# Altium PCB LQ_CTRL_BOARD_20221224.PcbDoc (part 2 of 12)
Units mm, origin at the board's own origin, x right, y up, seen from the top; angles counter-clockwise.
Board outline 260 x 142 mm, 6 copper layers (Top Layer, Mid-Layer 1, Mid-Layer 2, Mid-Layer 3, Mid-Layer 4, Bottom Layer); 1105 components, 1039 nets, 3898 pads, 1277 vias.
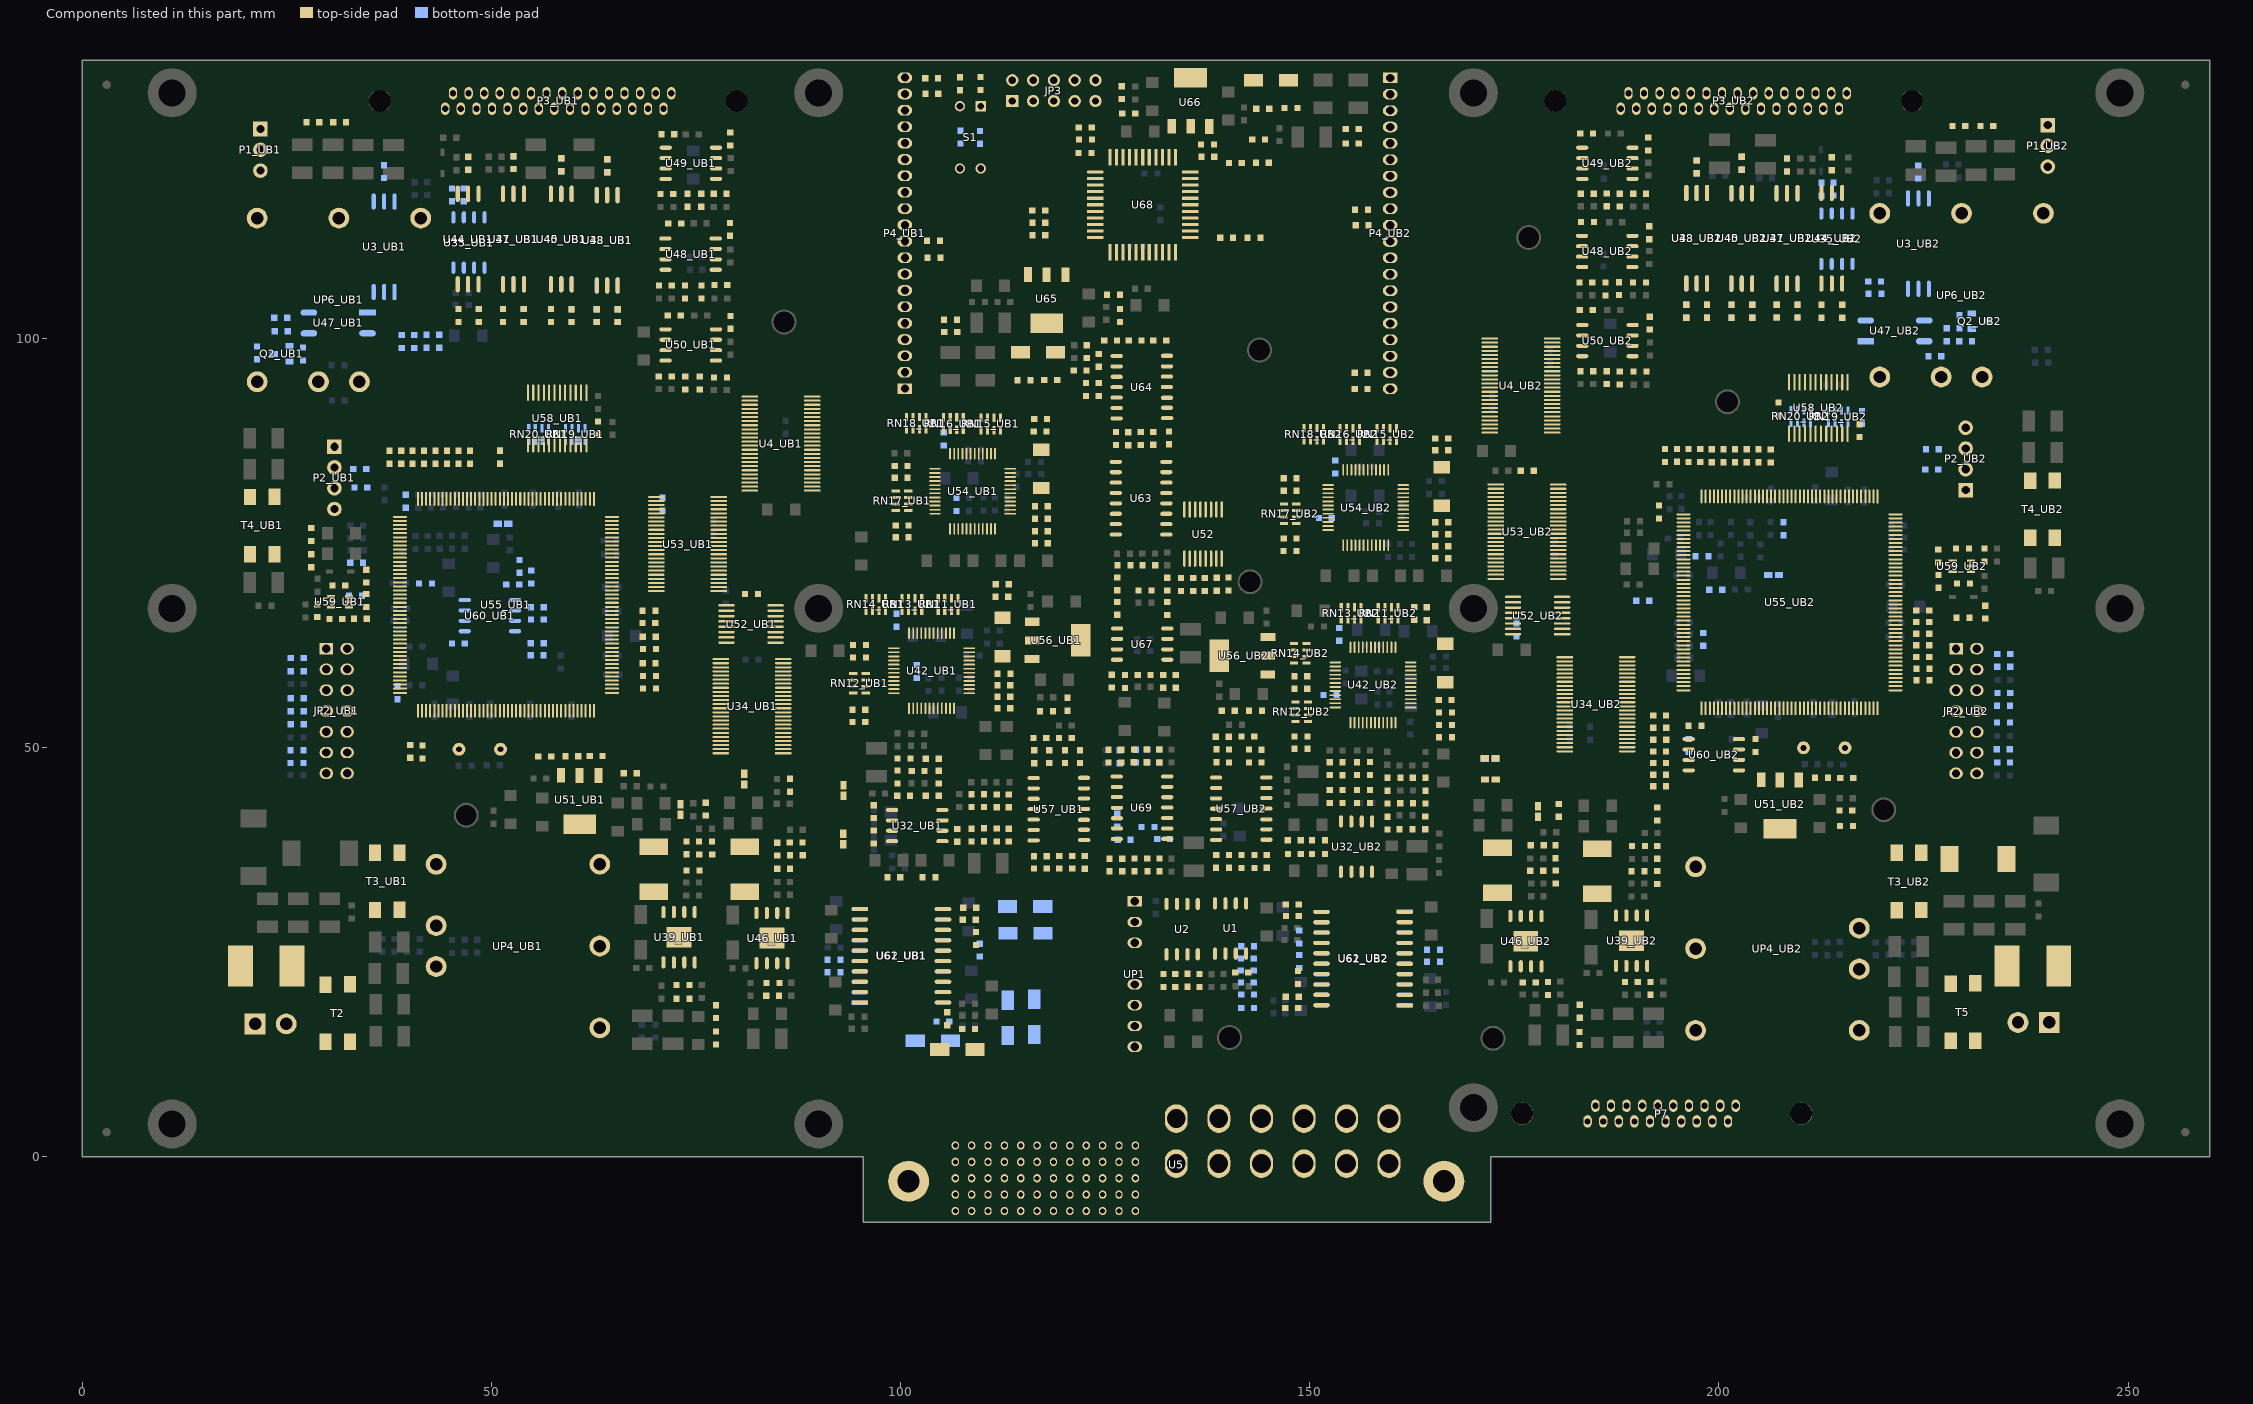
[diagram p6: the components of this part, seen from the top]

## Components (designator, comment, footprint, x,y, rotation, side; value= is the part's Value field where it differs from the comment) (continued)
DR2_UB2 "SMCJ30CA-TR" WP_SMC_DO214AB 228.168,36.373 r0 top (schematic designator DR2)
DR3 "SMCJ12CA-TR" WP_SMA_DO214AC 147.422,131.547 r180 top
DR4 "SMCJ5CA-TR" WP_SMA_DO214AC 114.656,98.298 r0 top
DR5 "SMAJ5.0CA" WP_SMA_DO214AC 101.803,14.173 r0 bottom
DR6 "SMAJ5.0CA" WP_SMA_DO214AC 117.373,30.582 r180 bottom
DR7 "SMAJ5.0CA" WP_SMA_DO214AC 104.8,13.106 r0 top
DR8 "SMAJ5.0CA" WP_SMA_DO214AC 117.424,27.305 r180 bottom
DR9 "SMAJ5.0CA" WP_SMA_DO214AC 116.357,14.935 r90 bottom
DR10 "SMAJ5.0CA" WP_SMA_DO214AC 113.106,14.808 r90 bottom
F1_UB1 "SMD2920R300SF" WP_2420 25.654,23.292 r180 top (schematic designator F1)
F1_UB2 "SMD2920R300SF" WP_2420 235.229,23.317 r0 top (schematic designator F1)
JP2_UB1 "JTAG" WP_IDC14 29.845,62.089 r270 top (schematic designator JP2)
JP2_UB2 "JTAG" WP_IDC14 228.981,62.078 r270 top (schematic designator JP2)
JP3 "Header 5X2" HDR2X5 113.665,129 r0 top
L3_UB1 "10uH/2A" WP_LBS6*6 69.85,37.897 r270 top (schematic designator L3)
L3_UB2 "10uH/2A" WP_LBS6*6 185.121,37.617 r270 top (schematic designator L3)
L4_UB1 "10uH/2A" WP_LBS6*6 80.975,37.871 r270 top (schematic designator L4)
L4_UB2 "10uH/2A" WP_LBS6*6 172.949,37.744 r270 top (schematic designator L4)
LED1 "LED" WP_0603_LED 145.009,121.463 r180 top
LED2 "LED" WP_0603_LED 143.993,112.293 r180 top
LED3 "LED" WP_0603_LED 109.779,131.928 r270 top
LED4 "LED" WP_0603_LED 107.264,131.902 r270 top
LED5_UB1 "LED" WP_0603_LED 27.991,76.81 r270 top (schematic designator LED5)
LED5_UB2 "LED" WP_0603_LED 232.537,67.335 r270 top (schematic designator LED5)
LED9_UB1 "LED" WP_0603_LED 77.47,18.517 r270 top (schematic designator LED9)
LED9_UB2 "LED" WP_0603_LED 183.007,18.567 r270 top (schematic designator LED9)
LED10_UB1 "LED" WP_0603_LED 27.407,126.39 r0 top (schematic designator LED10)
LED10_UB2 "LED" WP_0603_LED 233.528,125.959 r180 top (schematic designator LED10)
LED11_UB1 "LED" WP_0603_LED 60.63,48.946 r180 top (schematic designator LED11)
LED11_UB2 "LED" WP_0603_LED 214.732,42.316 r0 top (schematic designator LED11)
LED12_UB1 "LED" WP_0603_LED 120.416,56.083 r270 top (schematic designator LED12)
LED12_UB2 "LED" WP_0603_LED 139.268,54.487 r0 top (schematic designator LED12)
LED13_UB1 "LED" WP_0603_LED 40.107,50.317 r270 top (schematic designator LED13)
LED13_UB2 "LED" WP_0603_LED 191.973,53.899 r0 top (schematic designator LED13)
LED14_UB1 "LED" WP_0603_LED 107.62,28.956 r0 top (schematic designator LED14)
LED14_UB2 "LED" WP_0603_LED 148.655,19.558 r180 top (schematic designator LED14)
LED15_UB1 "LED" WP_0603_LED 105.715,17.653 r270 top (schematic designator LED15)
LED15_UB2 "LED" WP_0603_LED 148.655,30.81 r180 top (schematic designator LED15)
LED16 "LED" WP_0603_LED 114.3,94.869 r0 top
LED17 "LED" WP_0603_LED 148.514,128.143 r180 top
LED18 "LED" WP_0603_LED 126.822,102.006 r90 top
LED19 "LED" WP_0603_LED 127.045,130.81 r270 top
LED20 "LED" WP_0603_LED 123.393,124.282 r180 top
LED21 "LED" WP_0603_LED 136.728,123.673 r0 top
P1_UB1 "Header 3" WP_SIP3 21.793,125.578 r270 top (schematic designator P1)
P1_UB2 "Header 3" WP_SIP3 240.182,126.06 r270 top (schematic designator P1)
P2_UB1 "Header 4" WP_SIP4 30.836,86.766 r270 top (schematic designator P2)
P2_UB2 "Header 4" WP_SIP4 230.149,81.458 r90 top (schematic designator P2)
P3_UB1 "Header 15X2A" WP_CRM222-030 44.374,128.047 r180 bottom locked (schematic designator P3)
P3_UB2 "Header 15X2A" WP_CRM222-030 215.623,129.952 r0 bottom locked (schematic designator P3)
P4_UB1 "Header 20" WP_HEADER20S 100.533,93.853 r90 top (schematic designator P4)
P4_UB2 "Header 20" WP_HEADER20S 159.842,131.826 r270 top (schematic designator P4)
P7 "Header 10X2A" WP_CRM222-020 202.057,6.223 r0 bottom
P9_UB1 "Header 2" WP_LSIP2 21.133,16.231 r0 top (schematic designator P9)
P9_UB2 "Header 2" WP_LSIP2 240.36,16.408 r180 top (schematic designator P9)
Q2_UB1 "MMBT4401" WP_SOT23B 25.355,99.035 r270 bottom (schematic designator Q2)
Q2_UB2 "MMBT4401" WP_SOT23B 230.886,101.143 r90 bottom (schematic designator Q2)
R1 "0R" WP_0603R 105.334,102.26 r0 top
R2 "0R" WP_0603R 155.981,123.8 r180 top
R3_UB1 "100R" WP_0603R 45.999,84.684 r90 top (schematic designator R3)
R3_UB2 "100R" WP_0603R 203.403,84.861 r90 top (schematic designator R3)
R4_UB1 "100R" WP_0603R 47.396,84.684 r90 top (schematic designator R4)
R4_UB2 "100R" WP_0603R 204.826,84.861 r90 top (schematic designator R4)
R5 "2K" WP_0603R 134.264,70.714 r270 top
R6 "150R" WP_0603R 138.659,70.739 r270 top
R7 "150R" WP_0603R 140.081,70.764 r270 top
R8 "150R" WP_0603R 137.185,70.714 r270 top
R9 "150R" WP_0603R 135.763,70.714 r270 top
R10 "200R" WP_0603R 132.131,20.752 r90 top
R11 "200R" WP_0603R 135.077,20.777 r90 top
R12 "1K" WP_0603R 142.494,22.504 r180 top
R13 "200R" WP_0603R 133.579,20.752 r90 top
R14 "200R" WP_0603R 136.55,20.752 r90 top
R15_UB1 "0R" WP_0603R 38.532,55.905 r90 bottom (schematic designator R15)
R15_UB2 "0R" WP_0603R 198.095,64.008 r270 bottom (schematic designator R15)
R16_UB1 "0R" WP_0603R 41.173,70.053 r0 bottom (schematic designator R16)
R16_UB2 "0R" WP_0603R 198.831,69.291 r0 bottom (schematic designator R16)
R17_UB1 "1K5" WP_0603R 77.171,117.678 r0 top (schematic designator R17)
R17_UB2 "1K5" WP_0603R 189.535,117.653 r0 top (schematic designator R17)
R18_UB1 "1K5" WP_0603R 72.238,117.627 r180 top (schematic designator R18)
R18_UB2 "1K5" WP_0603R 184.709,117.653 r180 top (schematic designator R18)
R19_UB1 "1K5" WP_0603R 72.04,95.326 r180 top (schematic designator R19)
R19_UB2 "1K5" WP_0603R 184.658,95.987 r180 top (schematic designator R19)
R20_UB1 "1K5" WP_0603R 77.216,95.199 r0 top (schematic designator R20)
R20_UB2 "1K5" WP_0603R 189.572,95.936 r0 top (schematic designator R20)
R21_UB1 "1K5" WP_0603R 72.06,106.451 r180 top (schematic designator R21)
R21_UB2 "1K5" WP_0603R 184.531,106.807 r180 top (schematic designator R21)
R22_UB1 "1K5" WP_0603R 77.267,106.528 r0 top (schematic designator R22)
R22_UB2 "1K5" WP_0603R 189.509,106.832 r0 top (schematic designator R22)
R23_UB1 "150R" WP_0603R 62.89,101.981 r90 top (schematic designator R23)
R23_UB2 "150R" WP_0603R 198.557,102.514 r90 bottom (schematic designator R23)
R24 "10K" WP_0603R 131.648,36.449 r270 top
R25 "10K" WP_0603R 131.628,49.747 r270 top
R26_UB1 "150R" WP_0603R 43.643,98.857 r90 bottom (schematic designator R26)
R26_UB2 "150R" WP_0603R 218.237,106.959 r0 bottom (schematic designator R26)
R27_UB1 "150R" WP_0603R 42.093,98.857 r90 bottom (schematic designator R27)
R27_UB2 "150R" WP_0603R 218.288,105.435 r0 bottom (schematic designator R27)
R28_UB1 "33R" WP_0603R 36.906,119.583 r90 bottom (schematic designator R28)
R28_UB2 "33R" WP_0603R 224.358,119.532 r90 bottom (schematic designator R28)
R29_UB1 "33R" WP_0603R 34.722,84.023 r180 bottom (schematic designator R29)
R29_UB2 "33R" WP_0603R 225.222,83.972 r0 bottom (schematic designator R29)
R30_UB1 "33R" WP_0603R 33.274,81.763 r0 bottom (schematic designator R30)
R30_UB2 "33R" WP_0603R 226.873,86.436 r180 bottom (schematic designator R30)
R31 "2K" WP_0603R 141.707,121.437 r180 top
R32 "3K" WP_0603R 109.703,123.774 r90 bottom
R33 "2K" WP_0603R 140.64,112.293 r180 top
R34 "3K" WP_0603R 107.34,123.8 r90 bottom
R35 "10K" WP_0603R 116.129,112.598 r0 top
R36 "10K" WP_0603R 123.368,125.755 r180 top
R37 "10K" WP_0603R 116.129,114.122 r0 top
R38 "10K" WP_0603R 116.103,115.621 r0 top
R39_UB1 "10K" WP_0603R 105.283,88.494 r270 bottom (schematic designator R39)
R39_UB2 "10K" WP_0603R 153.111,85.065 r270 bottom (schematic designator R39)
R40_UB1 "10K" WP_0603R 99.517,66.345 r270 bottom (schematic designator R40)
R40_UB2 "10K" WP_0603R 153.619,64.618 r270 bottom (schematic designator R40)
R41_UB1 "2K" WP_0603R 27.991,72.034 r90 top (schematic designator R41)
R41_UB2 "2K" WP_0603R 229.033,65.862 r0 top (schematic designator R41)
R187 "10R" WP_0603R 126.492,40.335 r90 bottom
R188 "10R" WP_0603R 126.797,48.082 r90 bottom
R192_UB1 "10K" WP_0603R 45.212,116.738 r90 bottom (schematic designator R192)
R192_UB2 "10K" WP_0603R 212.547,117.424 r90 bottom (schematic designator R192)
R194_UB1 "2K" WP_0603R 46.634,116.738 r90 bottom (schematic designator R194)
R194_UB2 "2K" WP_0603R 214.02,117.45 r90 bottom (schematic designator R194)
R195_UB1 "10K" WP_0603R 104.663,47.168 r270 top (schematic designator R195)
R195_UB2 "10K" WP_0603R 164.16,44.729 r270 top (schematic designator R195)
R196_UB1 "100R" WP_0603R 104.663,44.12 r180 top (schematic designator R196)
R196_UB2 "100R" WP_0603R 164.109,41.586 r270 top (schematic designator R196)
R197_UB1 "620R" WP_0603R 108.681,42.723 r90 top (schematic designator R197)
R197_UB2 "620R" WP_0603R 152.451,46.634 r90 top (schematic designator R197)
R198_UB1 "100K" WP_0603R 104.267,34.163 r180 top (schematic designator R198)
R198_UB2 "100K" WP_0603R 147.345,36.982 r0 top (schematic designator R198)
R200_UB1 "100K" WP_0603R 108.687,38.506 r90 top (schematic designator R200)
R200_UB2 "100K" WP_0603R 152.451,43.231 r90 top (schematic designator R200)
R203_UB1 "100K" WP_0603R 103.099,48.641 r0 top (schematic designator R203)
R203_UB2 "100K" WP_0603R 162.585,46.31 r0 top (schematic designator R203)
R205_UB1 "100K" WP_0603R 110.211,38.557 r90 top (schematic designator R205)
R205_UB2 "100K" WP_0603R 154.026,43.231 r90 top (schematic designator R205)
R207_UB1 "3K" WP_0603R 106.949,40.056 r270 top (schematic designator R207)
R207_UB2 "3K" WP_0603R 151.867,36.982 r180 top (schematic designator R207)
R209_UB1 "3K3" WP_0603R 96.738,41.377 r90 top (schematic designator R209)
R209_UB2 "3K3" WP_0603R 160.985,40.005 r0 top (schematic designator R209)
R210_UB1 "10K" WP_0603R 77.47,13.716 r90 top (schematic designator R210)
R210_UB2 "10K" WP_0603R 182.982,13.665 r90 top (schematic designator R210)
R212_UB1 "20K" WP_0603R 101.371,47.117 r0 top (schematic designator R212)
R212_UB2 "20K" WP_0603R 161.061,43.186 r0 top (schematic designator R212)
R213_UB1 "620R" WP_0603R 110.2,42.723 r90 top (schematic designator R213)
R213_UB2 "620R" WP_0603R 154.026,46.627 r90 top (schematic designator R213)
R214_UB1 "3K" WP_0603R 96.738,39.853 r270 top (schematic designator R214)
R214_UB2 "3K" WP_0603R 151.867,38.659 r180 top (schematic designator R214)
R215_UB1 "150R" WP_0603R 51.44,102.006 r90 top (schematic designator R215)
R215_UB2 "150R" WP_0603R 209.601,102.54 r90 bottom (schematic designator R215)
R216_UB1 "100K" WP_0603R 99.974,34.138 r180 top (schematic designator R216)
R216_UB2 "100K" WP_0603R 148.895,38.659 r180 top (schematic designator R216)
R217_UB1 "620R" WP_0603R 113.222,42.697 r90 top (schematic designator R217)
R217_UB2 "620R" WP_0603R 157.378,46.66 r90 top (schematic designator R217)
R218_UB1 "150R" WP_0603R 65.456,101.981 r90 bottom (schematic designator R218)
R218_UB2 "150R" WP_0603R 196.012,102.514 r90 top (schematic designator R218)
R219_UB1 "100K" WP_0603R 99.644,48.653 r0 top (schematic designator R219)
R219_UB2 "100K" WP_0603R 159.512,46.304 r0 top (schematic designator R219)
R220_UB1 "100K" WP_0603R 113.233,38.506 r90 top (schematic designator R220)
R220_UB2 "100K" WP_0603R 157.378,43.223 r90 top (schematic designator R220)
R221_UB1 "10K" WP_0603R 99.644,47.193 r270 top (schematic designator R221)
R221_UB2 "10K" WP_0603R 159.512,44.729 r270 top (schematic designator R221)
R222_UB1 "100R" WP_0603R 101.168,44.12 r180 top (schematic designator R222)
R222_UB2 "100R" WP_0603R 159.512,41.554 r270 top (schematic designator R222)
R223_UB1 "33R" WP_0603R 64.16,120.294 r90 bottom (schematic designator R223)
R223_UB2 "33R" WP_0603R 197.287,120.167 r90 top (schematic designator R223)
R224_UB1 "33R" WP_0603R 52.71,120.675 r90 top (schematic designator R224)
R224_UB2 "33R" WP_0603R 208.33,120.396 r90 bottom (schematic designator R224)
R225_UB1 "100K" WP_0603R 111.76,38.532 r90 top (schematic designator R225)
R225_UB2 "100K" WP_0603R 155.778,43.231 r90 top (schematic designator R225)
R226_UB1 "150R" WP_0603R 53.98,102.006 r90 top (schematic designator R226)
R226_UB2 "150R" WP_0603R 207.061,102.54 r90 bottom (schematic designator R226)
R227_UB1 "150R" WP_0603R 62.89,101.981 r90 bottom (schematic designator R227)
R227_UB2 "150R" WP_0603R 198.552,102.514 r90 top (schematic designator R227)
R228_UB1 "620R" WP_0603R 111.749,42.697 r90 top (schematic designator R228)
R228_UB2 "620R" WP_0603R 155.778,46.634 r90 top (schematic designator R228)
R229_UB1 "0R" WP_JS2 73.127,41.656 r90 top (schematic designator R229)
R229_UB2 "0R" WP_JS2 172.822,48.641 r180 bottom (schematic designator R229)
R230_UB1 "3K" WP_0603R 82.575,68.758 r180 top (schematic designator R230)
R230_UB2 "3K" WP_0603R 175.285,65.176 r270 bottom (schematic designator R230)
R231_UB1 "0R" WP_JS2 93.019,38.049 r90 top (schematic designator R231)
R231_UB2 "0R" WP_JS2 171.298,46.101 r0 top (schematic designator R231)
R232_UB1 "150R" WP_0603R 57.282,102.006 r90 top (schematic designator R232)
R232_UB2 "150R" WP_0603R 204.069,102.514 r90 bottom (schematic designator R232)
R233_UB1 "150R" WP_0603R 53.98,102.006 r90 bottom (schematic designator R233)
R233_UB2 "150R" WP_0603R 207.061,102.54 r90 top (schematic designator R233)
R234_UB1 "3K" WP_0603R 76.2,43.256 r270 top (schematic designator R234)
R234_UB2 "3K" WP_0603R 192.481,41.097 r90 top (schematic designator R234)
R235_UB1 "33R" WP_0603R 52.71,120.675 r90 bottom (schematic designator R235)
R235_UB2 "33R" WP_0603R 208.33,120.396 r90 top (schematic designator R235)
R236_UB1 "30K" WP_0603R 72.644,20.98 r0 top (schematic designator R236)
R236_UB2 "30K" WP_0603R 188.519,21.361 r0 top (schematic designator R236)
R237_UB1 "33R" WP_0603R 58.552,120.421 r90 top (schematic designator R237)
R237_UB2 "33R" WP_0603R 202.799,120.599 r90 bottom (schematic designator R237)
R238_UB1 "51K" WP_0603R 76.962,38.532 r180 top (schematic designator R238)
R238_UB2 "51K" WP_0603R 192.456,36.398 r90 top (schematic designator R238)
R239_UB1 "2K" WP_0603R 73.863,38.532 r270 top (schematic designator R239)
R239_UB2 "2K" WP_0603R 190.957,37.973 r180 top (schematic designator R239)
R240_UB1 "150R" WP_0603R 59.817,101.981 r90 top (schematic designator R240)
R240_UB2 "150R" WP_0603R 201.529,102.514 r90 bottom (schematic designator R240)
R241_UB1 "150R" WP_0603R 51.44,102.006 r90 bottom (schematic designator R241)
R241_UB2 "150R" WP_0603R 209.601,102.54 r90 top (schematic designator R241)
R242_UB1 "10K" WP_0603R 75.418,36.932 r0 top (schematic designator R242)
R242_UB2 "10K" WP_0603R 192.481,33.325 r90 top (schematic designator R242)
R243_UB1 "100K" WP_0603R 74.219,19.304 r180 top (schematic designator R243)
R243_UB2 "100K" WP_0603R 191.643,21.361 r270 top (schematic designator R243)
R244_UB1 "10K" WP_0603R 113.436,59.004 r180 top (schematic designator R244)
R244_UB2 "10K" WP_0603R 167.335,55.796 r180 top (schematic designator R244)
R245_UB1 "36K" WP_0603R 75.438,34.976 r180 top (schematic designator R245)
R245_UB2 "36K" WP_0603R 190.906,34.874 r180 top (schematic designator R245)
R246_UB1 "150R" WP_0603R 45.979,102.006 r90 top (schematic designator R246)
R246_UB2 "150R" WP_0603R 212.527,102.514 r90 top (schematic designator R246)
R247_UB1 "150R" WP_0603R 65.456,101.981 r90 top (schematic designator R247)
R247_UB2 "150R" WP_0603R 196.012,102.514 r90 bottom (schematic designator R247)
R248_UB1 "33R" WP_0603R 64.166,120.294 r90 top (schematic designator R248)
R248_UB2 "33R" WP_0603R 197.287,120.167 r90 bottom (schematic designator R248)
R249_UB1 "150R" WP_0603R 59.817,101.981 r90 bottom (schematic designator R249)
R249_UB2 "150R" WP_0603R 201.529,102.514 r90 top (schematic designator R249)
R250_UB1 "3K" WP_0603R 21.387,99.009 r270 bottom (schematic designator R250)
R250_UB2 "3K" WP_0603R 227.178,97.815 r180 bottom (schematic designator R250)
R251_UB1 "33R" WP_0603R 58.552,120.421 r90 bottom (schematic designator R251)
R251_UB2 "33R" WP_0603R 202.799,120.599 r90 top (schematic designator R251)
R252_UB1 "33R" WP_0603R 47.174,120.599 r90 top (schematic designator R252)
R252_UB2 "33R" WP_0603R 213.797,120.548 r90 top (schematic designator R252)
R253_UB1 "150R" WP_0603R 48.463,102.006 r90 top (schematic designator R253)
R253_UB2 "150R" WP_0603R 215.067,102.514 r90 top (schematic designator R253)
R254_UB1 "150R" WP_0603R 57.282,102.006 r90 bottom (schematic designator R254)
R254_UB2 "150R" WP_0603R 204.069,102.514 r90 top (schematic designator R254)
R255_UB1 "2K" WP_0603R 113.172,68.428 r180 top (schematic designator R255)
R255_UB2 "2K" WP_0603R 164.313,67.132 r270 top (schematic designator R255)
R256_UB1 "10K" WP_0603R 25.07,102.514 r180 bottom (schematic designator R256)
R256_UB2 "10K" WP_0603R 229.362,99.644 r0 bottom (schematic designator R256)
R257_UB1 "1K" WP_0603R 40.595,100.406 r270 bottom (schematic designator R257)
R257_UB2 "1K" WP_0603R 217.5,91.135 r270 bottom (schematic designator R257)
R258_UB1 "10K" WP_0603R 39.065,100.406 r270 bottom (schematic designator R258)
R258_UB2 "10K" WP_0603R 207.289,90.576 r90 top (schematic designator R258)
R259_UB1 "0R" WP_JS2 80.899,45.364 r90 top (schematic designator R259)
R259_UB2 "0R" WP_JS2 177.902,41.402 r90 top (schematic designator R259)
R260_UB1 "10K" WP_0603R 23.546,100.863 r0 bottom (schematic designator R260)
R260_UB2 "10K" WP_0603R 227.838,101.219 r270 bottom (schematic designator R260)
R261_UB1 "5K1" WP_0603R 101.981,58.496 r90 bottom (schematic designator R261)
R261_UB2 "5K1" WP_0603R 153.264,56.413 r180 bottom (schematic designator R261)
R262_UB1 "2K" WP_0603R 86.512,46.177 r270 top (schematic designator R262)
R262_UB2 "2K" WP_0603R 180.442,41.529 r90 top (schematic designator R262)
R263_UB1 "30K" WP_0603R 83.642,21.234 r0 top (schematic designator R263)
R263_UB2 "30K" WP_0603R 176.047,21.285 r0 top (schematic designator R263)
R264_UB1 "10K" WP_0603R 27,98.882 r270 bottom (schematic designator R264)
R264_UB2 "10K" WP_0603R 229.387,101.244 r90 bottom (schematic designator R264)
R265_UB1 "1K" WP_0603R 73.665,106.451 r270 top (schematic designator R265)
R265_UB2 "1K" WP_0603R 186.131,106.807 r270 top (schematic designator R265)
R266_UB1 "1K" WP_0603R 75.647,117.653 r270 top (schematic designator R266)
R266_UB2 "1K" WP_0603R 187.884,117.678 r270 top (schematic designator R266)
R267_UB1 "1K" WP_0603R 73.691,95.326 r270 top (schematic designator R267)
R267_UB2 "1K" WP_0603R 186.296,95.987 r270 top (schematic designator R267)
R268_UB1 "30K" WP_0603R 88.036,38.405 r180 top (schematic designator R268)
R268_UB2 "30K" WP_0603R 180.035,36.474 r90 top (schematic designator R268)
R269_UB1 "1K5" WP_0603R 84.938,38.379 r270 top (schematic designator R269)
R269_UB2 "1K5" WP_0603R 178.587,38.049 r180 top (schematic designator R269)
R270_UB1 "1K" WP_0603R 71.628,114.046 r0 top (schematic designator R270)
R270_UB2 "1K" WP_0603R 183.159,114.224 r0 top (schematic designator R270)
R271_UB1 "1K" WP_0603R 79.197,125.146 r270 top (schematic designator R271)
R271_UB2 "1K" WP_0603R 191.364,124.536 r270 top (schematic designator R271)
R272_UB1 "1K" WP_0603R 71.577,102.794 r0 top (schematic designator R272)
R272_UB2 "1K" WP_0603R 183.007,103.454 r0 top (schematic designator R272)
R273_UB1 "10K" WP_0603R 86.487,36.83 r0 top (schematic designator R273)
R273_UB2 "10K" WP_0603R 180.066,33.401 r90 top (schematic designator R273)
R274_UB1 "100K" WP_0603R 85.166,19.66 r180 top (schematic designator R274)
R274_UB2 "100K" WP_0603R 179.121,21.336 r270 top (schematic designator R274)
R275_UB1 "10K" WP_0603R 32.258,126.416 r180 top (schematic designator R275)
R275_UB2 "10K" WP_0603R 228.54,125.959 r0 top (schematic designator R275)
R276_UB1 "36K" WP_0603R 86.512,35.179 r180 top (schematic designator R276)
R276_UB2 "36K" WP_0603R 178.537,34.95 r180 top (schematic designator R276)
R277_UB1 "0R" WP_0603R 34.722,70.155 r90 top (schematic designator R277)
R277_UB2 "0R" WP_0603R 192.684,77.996 r90 top (schematic designator R277)
R278_UB1 "10K" WP_0603R 95.773,61.011 r180 top (schematic designator R278)
R278_UB2 "10K" WP_0603R 149.708,57.175 r180 top (schematic designator R278)
R279_UB1 "10K" WP_0603R 95.773,62.535 r180 top (schematic designator R279)
R279_UB2 "10K" WP_0603R 149.708,58.699 r180 top (schematic designator R279)
R280_UB1 "10K" WP_0603R 95.707,53.111 r180 top (schematic designator R280)
R280_UB2 "10K" WP_0603R 149.733,49.86 r180 top (schematic designator R280)
R281_UB1 "10K" WP_0603R 95.707,54.61 r180 top (schematic designator R281)
R281_UB2 "10K" WP_0603R 149.733,51.359 r180 top (schematic designator R281)
R282_UB1 "1K" WP_0603R 75.692,106.451 r270 top (schematic designator R282)
R282_UB2 "1K" WP_0603R 187.782,106.858 r270 top (schematic designator R282)
R283_UB1 "0R" WP_JS2 93.04,45.517 r270 top (schematic designator R283)
R283_UB2 "0R" WP_JS2 171.272,48.692 r0 top (schematic designator R283)
R284_UB1 "10K" WP_0603R 111.851,54.813 r0 top (schematic designator R284)
R284_UB2 "10K" WP_0603R 165.811,51.253 r0 top (schematic designator R284)
R285_UB1 "1K" WP_0603R 73.97,117.653 r270 top (schematic designator R285)
R285_UB2 "1K" WP_0603R 186.309,117.704 r270 top (schematic designator R285)
R286_UB1 "1K" WP_0603R 75.469,95.326 r270 top (schematic designator R286)
R286_UB2 "1K" WP_0603R 187.896,95.936 r270 top (schematic designator R286)
R287_UB1 "10K" WP_0603R 111.851,56.207 r0 top (schematic designator R287)
R287_UB2 "10K" WP_0603R 165.811,52.748 r0 top (schematic designator R287)
R288_UB1 "1K" WP_0603R 79.172,114.097 r270 top (schematic designator R288)
R288_UB2 "1K" WP_0603R 191.491,113.69 r270 top (schematic designator R288)
R289_UB1 "10R" WP_0603R 55.753,48.895 r0 top (schematic designator R289)
R289_UB2 "10R" WP_0603R 214.808,40.411 r0 top (schematic designator R289)
R290_UB1 "10K" WP_0603R 111.851,57.607 r0 top (schematic designator R290)
R290_UB2 "10K" WP_0603R 165.811,54.272 r0 top (schematic designator R290)
R291_UB1 "1K" WP_0603R 70.79,124.943 r0 top (schematic designator R291)
R291_UB2 "1K" WP_0603R 183.058,125.019 r0 top (schematic designator R291)
R292_UB1 "1K" WP_0603R 79.223,102.743 r270 top (schematic designator R292)
R292_UB2 "1K" WP_0603R 191.547,102.641 r270 top (schematic designator R292)
R293_UB1 "10K" WP_0603R 111.648,69.952 r0 top (schematic designator R293)
R293_UB2 "10K" WP_0603R 162.789,65.608 r90 top (schematic designator R293)
R294_UB1 "15R" WP_0603R 67.767,46.863 r180 top (schematic designator R294)
R294_UB2 "15R" WP_0603R 216.408,46.279 r180 top (schematic designator R294)
R295_UB1 "240R" WP_0603R 63.602,48.971 r180 top (schematic designator R295)
R295_UB2 "240R" WP_0603R 211.76,46.304 r0 top (schematic designator R295)
R296_UB1 "0R" WP_JS2 50.648,77.356 r0 bottom (schematic designator R296)
R296_UB2 "0R" WP_JS2 205.918,71.095 r0 bottom (schematic designator R296)
R297_UB1 "100R" WP_0603R 41.783,84.684 r90 top (schematic designator R297)
R297_UB2 "100R" WP_0603R 199.136,84.861 r90 top (schematic designator R297)
R298_UB1 "100R" WP_0603R 37.567,84.684 r90 top (schematic designator R298)
R298_UB2 "100R" WP_0603R 194.869,84.912 r90 top (schematic designator R298)
R299_UB1 "0R" WP_0603R 34.188,68.555 r180 bottom (schematic designator R299)
R299_UB2 "0R" WP_0603R 191.491,67.945 r180 bottom (schematic designator R299)
R300_UB1 "100R" WP_0603R 43.18,84.684 r90 top (schematic designator R300)
R300_UB2 "100R" WP_0603R 200.558,84.861 r90 top (schematic designator R300)
R301_UB1 "100R" WP_0603R 38.989,84.684 r90 top (schematic designator R301)
R301_UB2 "100R" WP_0603R 196.297,84.887 r90 top (schematic designator R301)
R302_UB1 "4K7" WP_0603R 25.502,59.309 r0 bottom (schematic designator R302)
R302_UB2 "4K7" WP_0603R 235.59,59.868 r180 bottom (schematic designator R302)
R303_UB1 "10K" WP_0603R 25.502,60.935 r0 bottom (schematic designator R303)
R303_UB2 "10K" WP_0603R 235.59,61.443 r180 bottom (schematic designator R303)
R304_UB1 "100R" WP_0603R 44.577,84.684 r90 top (schematic designator R304)
R304_UB2 "100R" WP_0603R 201.981,84.861 r90 top (schematic designator R304)
R305_UB1 "100R" WP_0603R 40.386,84.684 r90 top (schematic designator R305)
R305_UB2 "100R" WP_0603R 197.714,84.887 r90 top (schematic designator R305)
R306_UB1 "10K" WP_0603R 25.502,56.032 r0 bottom (schematic designator R306)
R306_UB2 "10K" WP_0603R 235.61,56.667 r180 bottom (schematic designator R306)
R307_UB1 "10K" WP_0603R 25.502,54.432 r0 bottom (schematic designator R307)
R307_UB2 "10K" WP_0603R 235.56,55.118 r180 bottom (schematic designator R307)
R308_UB1 "10K" WP_0603R 118.008,79.477 r180 top (schematic designator R308)
R308_UB2 "10K" WP_0603R 166.929,77.52 r180 top (schematic designator R308)
R309_UB1 "10K" WP_0603R 25.502,52.857 r0 bottom (schematic designator R309)
R309_UB2 "10K" WP_0603R 235.56,53.072 r180 bottom (schematic designator R309)
R310_UB1 "2K" WP_0603R 117.856,88.621 r180 top (schematic designator R310)
R310_UB2 "2K" WP_0603R 166.918,86.336 r180 top (schematic designator R310)
R311_UB1 "4K7" WP_0603R 27.051,48.108 r180 bottom (schematic designator R311)
R311_UB2 "4K7" WP_0603R 234.01,48.17 r0 bottom (schematic designator R311)
R312_UB1 "4K7" WP_0603R 25.476,49.657 r0 bottom (schematic designator R312)
R312_UB2 "4K7" WP_0603R 235.534,49.784 r180 bottom (schematic designator R312)
R313_UB1 "3K" WP_0603R 70.917,80.518 r270 bottom (schematic designator R313)
R313_UB2 "3K" WP_0603R 177.368,83.82 r180 top (schematic designator R313)
R314_UB1 "5K1" WP_0603R 106.858,80.493 r270 bottom (schematic designator R314)
R314_UB2 "5K1" WP_0603R 152.705,78.054 r180 bottom (schematic designator R314)
R315_UB1 "33R" WP_0603R 68.553,62.027 r0 top (schematic designator R315)
R315_UB2 "33R" WP_0603R 224.13,62.484 r0 top (schematic designator R315)
R316_UB1 "33R" WP_0603R 68.478,66.726 r0 top (schematic designator R316)
R316_UB2 "33R" WP_0603R 224.13,66.751 r0 top (schematic designator R316)
R317_UB1 "33R" WP_0603R 68.553,57.201 r0 top (schematic designator R317)
R317_UB2 "33R" WP_0603R 224.155,58.217 r0 top (schematic designator R317)
R318_UB1 "10K" WP_0603R 100.863,82.956 r180 top (schematic designator R318)
R318_UB2 "10K" WP_0603R 148.401,81.381 r180 top (schematic designator R318)
R319_UB1 "33R" WP_0603R 68.465,65.202 r0 top (schematic designator R319)
R319_UB2 "33R" WP_0603R 224.13,65.329 r0 top (schematic designator R319)
R320_UB1 "10K" WP_0603R 100.863,84.404 r180 top (schematic designator R320)
R320_UB2 "10K" WP_0603R 148.401,82.905 r180 top (schematic designator R320)
R321_UB1 "10K" WP_0603R 100.99,75.692 r180 top (schematic designator R321)
R321_UB2 "10K" WP_0603R 148.376,74.02 r180 top (schematic designator R321)
R322_UB1 "33R" WP_0603R 68.516,63.551 r0 top (schematic designator R322)
R322_UB2 "33R" WP_0603R 224.13,63.906 r0 top (schematic designator R322)
R323_UB1 "10K" WP_0603R 100.99,77.14 r180 top (schematic designator R323)
R323_UB2 "10K" WP_0603R 148.401,75.539 r180 top (schematic designator R323)
R324_UB1 "10K" WP_0603R 116.434,74.955 r0 top (schematic designator R324)
R324_UB2 "10K" WP_0603R 165.354,73.126 r0 top (schematic designator R324)
R325_UB1 "22K" WP_0603R 32.766,72.568 r0 bottom (schematic designator R325)
R325_UB2 "22K" WP_0603R 198.73,73.381 r180 bottom (schematic designator R325)
R326_UB1 "10K" WP_0603R 116.434,76.434 r0 top (schematic designator R326)
R326_UB2 "10K" WP_0603R 165.354,74.599 r0 top (schematic designator R326)
R327_UB1 "10K" WP_0603R 116.434,77.958 r0 top (schematic designator R327)
R327_UB2 "10K" WP_0603R 165.354,76.073 r0 top (schematic designator R327)
R328_UB1 "0R" WP_0603R 39.548,80.874 r270 bottom (schematic designator R328)
R328_UB2 "0R" WP_0603R 193.421,86.462 r270 top (schematic designator R328)
R329_UB1 "10K" WP_0603R 116.332,90.145 r0 top (schematic designator R329)
R329_UB2 "10K" WP_0603R 165.354,87.757 r0 top (schematic designator R329)
R330_UB1 "2K" WP_0603R 117.063,54.432 r0 top (schematic designator R330)
R330_UB2 "2K" WP_0603R 144.17,54.487 r180 top (schematic designator R330)
R331_UB1 "10K" WP_0603R 70.077,60.3 r180 top (schematic designator R331)
R331_UB2 "10K" WP_0603R 225.704,61.062 r180 top (schematic designator R331)
R332_UB1 "10K/0.1%" WP_0603R 116.357,48.082 r90 top (schematic designator R332)
R332_UB2 "10K/0.1%" WP_0603R 138.608,48.209 r90 top (schematic designator R332)
R333_UB1 "1K/0.1%" WP_0603R 118.186,49.682 r270 top (schematic designator R333)
R333_UB2 "1K/0.1%" WP_0603R 140.132,49.759 r270 top (schematic designator R333)
R334_UB1 "3K/0.1%" WP_0603R 122.504,35.179 r90 top (schematic designator R334)
R334_UB2 "3K/0.1%" WP_0603R 144.755,35.306 r90 top (schematic designator R334)
R335_UB1 "3K/0.1%" WP_0603R 120.98,35.204 r180 top (schematic designator R335)
R335_UB2 "3K/0.1%" WP_0603R 143.256,35.281 r180 top (schematic designator R335)
R336_UB1 "2K" WP_0603R 51.054,86.258 r270 bottom (schematic designator R336)
R336_UB2 "2K" WP_0603R 207.899,75.946 r90 bottom (schematic designator R336)
R337_UB1 "0R" WP_0603R 51.054,86.258 r270 top (schematic designator R337)
R337_UB2 "0R" WP_0603R 206.35,86.411 r270 top (schematic designator R337)
R338_UB1 "1K/0.1%" WP_0603R 116.25,51.181 r0 top (schematic designator R338)
R338_UB2 "1K/0.1%" WP_0603R 138.532,51.308 r0 top (schematic designator R338)
R339_UB1 "1K/0.1%" WP_0603R 121.945,49.682 r270 top (schematic designator R339)
R339_UB2 "1K/0.1%" WP_0603R 144.12,49.733 r270 top (schematic designator R339)
R340_UB1 "620R/0.1%" WP_0603R 120.98,36.754 r180 top (schematic designator R340)
R340_UB2 "620R/0.1%" WP_0603R 143.256,36.881 r180 top (schematic designator R340)
R341_UB1 "2K/0.1%" WP_0603R 120.929,51.156 r180 top (schematic designator R341)
R341_UB2 "2K/0.1%" WP_0603R 143.231,51.333 r180 top (schematic designator R341)
R342_UB1 "100R/0.1%" WP_0603R 116.307,36.728 r0 top (schematic designator R342)
R342_UB2 "100R/0.1%" WP_0603R 138.582,36.855 r0 top (schematic designator R342)
R343_UB1 "0R" WP_0603R 117.881,35.204 r180 top (schematic designator R343)
R343_UB2 "0R" WP_0603R 140.132,35.306 r180 top (schematic designator R343)
R344_UB1 "10K/0.1%" WP_0603R 120.117,49.682 r270 top (schematic designator R344)
R344_UB2 "10K/0.1%" WP_0603R 142.596,49.759 r270 top (schematic designator R344)
R345_UB1 "33R" WP_0603R 68.555,58.725 r0 top (schematic designator R345)
R345_UB2 "33R" WP_0603R 224.155,59.639 r0 top (schematic designator R345)
R346_UB1 "10K" WP_0603R 34.722,67.183 r90 top (schematic designator R346)
R346_UB2 "10K" WP_0603R 226.822,71.095 r270 top (schematic designator R346)
R347_UB1 "2K" WP_0603R 41.605,50.241 r270 top (schematic designator R347)
R347_UB2 "2K" WP_0603R 197.866,52.654 r180 top (schematic designator R347)
R348_UB1 "10R" WP_0603R 54.825,62.738 r0 bottom (schematic designator R348)
R348_UB2 "10R" WP_0603R 193.564,52.426 r180 top (schematic designator R348)
R349_UB1 "10R" WP_0603R 53.442,71.349 r90 bottom (schematic designator R349)
R349_UB2 "10R" WP_0603R 193.548,46.685 r180 top (schematic designator R349)
R350_UB1 "10R" WP_0603R 54.889,70.053 r90 bottom (schematic designator R350)
R350_UB2 "10R" WP_0603R 193.548,49.53 r180 top (schematic designator R350)
R352_UB1 "10K" WP_0603R 63.043,88.265 r90 top (schematic designator R352)
R352_UB2 "10K" WP_0603R 217.17,89.51 r270 top (schematic designator R352)
R353_UB1 "100K" WP_0603R 32.163,69.787 r180 top (schematic designator R353)
R353_UB2 "100K" WP_0603R 229.108,70.028 r0 top (schematic designator R353)
R355_UB1 "1K" WP_0603R 34.798,65.735 r180 top (schematic designator R355)
R355_UB2 "1K" WP_0603R 226.797,72.613 r90 top (schematic designator R355)
R356_UB1 "10K" WP_0603R 31.801,65.71 r180 top (schematic designator R356)
R356_UB2 "10K" WP_0603R 228.981,74.32 r0 top (schematic designator R356)
R358_UB1 "10K" WP_0603R 54.839,65.659 r0 bottom (schematic designator R358)
R358_UB2 "10K" WP_0603R 204.47,49.454 r90 top (schematic designator R358)
R359_UB1 "100K" WP_0603R 28.727,65.938 r90 top (schematic designator R359)
R359_UB2 "100K" WP_0603R 232.455,74.32 r270 top (schematic designator R359)
R361_UB1 "10K" WP_0603R 53.416,69.926 r180 bottom (schematic designator R361)
R361_UB2 "10K" WP_0603R 193.548,45.263 r180 top (schematic designator R361)
R362_UB1 "10K" WP_0603R 46.761,62.713 r180 bottom (schematic designator R362)
R362_UB2 "10K" WP_0603R 196.312,51.029 r270 bottom (schematic designator R362)
R363_UB1 "10K" WP_0603R 54.813,61.29 r0 bottom (schematic designator R363)
R363_UB2 "10K" WP_0603R 193.564,50.952 r180 top (schematic designator R363)
R364_UB1 "10K" WP_0603R 54.839,67.132 r0 bottom (schematic designator R364)
R364_UB2 "10K" WP_0603R 193.548,48.108 r180 top (schematic designator R364)
R365_UB1 "3K" WP_0603R 107.676,30.429 r0 top (schematic designator R365)
R365_UB2 "3K" WP_0603R 148.604,18.161 r180 top (schematic designator R365)
R366_UB1 "120R" WP_0603R 109.22,25.883 r90 top (schematic designator R366)
R366_UB2 "120R" WP_0603R 148.579,22.682 r270 top (schematic designator R366)
R367_UB1 "10K" WP_0603R 105.969,16.535 r180 bottom (schematic designator R367)
R367_UB2 "10K" WP_0603R 148.717,26.06 r90 bottom (schematic designator R367)
R368_UB1 "33R" WP_0603R 92.659,22.555 r180 bottom (schematic designator R368)
R368_UB2 "33R" WP_0603R 164.338,25.298 r0 bottom (schematic designator R368)
R369_UB1 "33R" WP_0603R 92.659,24.079 r180 bottom (schematic designator R369)
R369_UB2 "33R" WP_0603R 164.338,23.825 r0 bottom (schematic designator R369)
R370_UB1 "120R" WP_0603R 109.677,24.46 r90 bottom (schematic designator R370)
R370_UB2 "120R" WP_0603R 148.717,24.638 r270 bottom (schematic designator R370)
R371_UB1 "2K" WP_0603R 109.118,15.621 r180 top (schematic designator R371)
R371_UB2 "2K" WP_0603R 148.666,29.413 r180 top (schematic designator R371)
R372 "10K/0.1%" WP_0603R 124.892,99.72 r0 top
R373 "1K/0.1%" WP_0603R 127.889,99.746 r0 top
R374 "10R" WP_0603R 122.733,96.063 r180 top
R375 "3K/0.1%" WP_0603R 130.886,86.995 r90 top
R376 "3K/0.1%" WP_0603R 132.817,87.046 r90 top
R377 "10K" WP_0603R 117.577,94.894 r0 top
R378 "10R" WP_0603R 122.682,94.539 r270 top
R379 "1K/0.1%" WP_0603R 124.231,96.52 r90 top
R380 "1K/0.1%" WP_0603R 130.886,99.746 r0 top
R381 "620R/0.1%" WP_0603R 129.362,88.544 r270 top
R382 "2K/0.1%" WP_0603R 122.758,99.162 r270 top
R383 "100R/0.1%" WP_0603R 127.838,88.519 r270 top
R384 "0R" WP_0603R 126.34,86.97 r90 top
R385 "10K/0.1%" WP_0603R 124.231,94.539 r270 top
R386 "0R" WP_0603R 105.359,100.787 r0 top
R387 "3K" WP_0603R 145.059,128.067 r180 top
R388 "0R" WP_0603R 155.981,125.578 r180 top
R389 "0R" WP_0603R 144.551,124.308 r180 top
R390 "1K5" WP_0603R 125.247,105.334 r0 top
R391 "0R" WP_0603R 103.048,129.896 r0 top
R392 "0R" WP_0603R 103.022,131.775 r0 top
R393 "0R" WP_0603R 103.302,109.855 r0 top
R394 "0R" WP_0603R 103.251,111.912 r0 top
R395 "2K" WP_0603R 128.676,127.457 r180 top
R396 "10K" WP_0603R 132.588,70.76 r270 top
R397 "100R" WP_0603R 132.588,67.767 r270 top
R398 "100K" WP_0603R 133.629,58.877 r270 top
R399 "100K" WP_0603R 129.56,72.275 r0 top
R400 "3K" WP_0603R 132.105,58.877 r270 top
R401 "3K3" WP_0603R 128.981,58.877 r0 top
R403 "20K" WP_0603R 129.083,69.19 r0 top
R404 "3K" WP_0603R 127.432,58.852 r270 top
R405 "100K" WP_0603R 125.806,57.328 r90 top
R406 "100K" WP_0603R 126.517,72.259 r0 top
R407 "10K" WP_0603R 126.492,70.79 r270 top
R408 "100R" WP_0603R 126.492,67.793 r270 top
R409 "10R" WP_0603R 128.118,38.735 r180 bottom
R410 "10R" WP_0603R 131.369,38.837 r0 bottom
R411 "620R" WP_0603R 128.58,36.437 r0 top
R412 "100K" WP_0603R 125.527,36.424 r0 top
R413 "0R" WP_0603R 143.205,19.837 r180 bottom
R415 "0R" WP_0603R 143.205,18.161 r180 bottom
R416 "100K" WP_0603R 125.527,34.874 r0 top
R417 "10R" WP_0603R 129.464,40.284 r0 bottom
R418 "620R" WP_0603R 128.6,34.874 r0 top
R419 "10R" WP_0603R 128.753,48.158 r90 bottom
R420 "10R" WP_0603R 131.648,48.184 r90 bottom
R421 "0R" WP_0603R 141.605,21.285 r0 bottom
R422 "0R" WP_0603R 141.58,22.758 r0 bottom
R423 "0R" WP_0603R 141.605,24.232 r0 bottom
R424 "0R" WP_0603R 141.63,25.73 r0 bottom
R425 "620R" WP_0603R 128.529,49.772 r0 top
R426 "100K" WP_0603R 125.405,49.721 r0 top
R428 "100K" WP_0603R 125.405,48.172 r0 top
R429 "10R" WP_0603R 130.15,48.184 r90 bottom
R430 "620R" WP_0603R 128.504,48.197 r0 top
R431 "2K" WP_0603R 123.342,122.657 r180 top
R432 "0R" WP_0603R 157.074,95.809 r180 top
R433 "0R" WP_0603R 157.074,93.802 r180 top
R434 "0R" WP_0603R 157.124,115.722 r180 top
R435 "2K" WP_0603R 136.779,122.174 r0 top
R436 "0R" WP_0603R 157.201,113.817 r180 top
RN11_UB1 "10K" WP_RP4 108.204,66.116 r180 top (schematic designator RN11)
RN11_UB2 "10K" WP_RP4 161.968,65.024 r180 top (schematic designator RN11)
RN12_UB1 "10K" WP_RP4 93.624,55.474 r90 top (schematic designator RN12)
RN12_UB2 "10K" WP_RP4 147.65,51.994 r90 top (schematic designator RN12)
RN13_UB1 "10K" WP_RP4 103.784,66.116 r180 top (schematic designator RN13)
RN13_UB2 "10K" WP_RP4 157.447,65.024 r180 top (schematic designator RN13)
RN14_UB1 "10K" WP_RP4 99.365,66.116 r180 top (schematic designator RN14)
RN14_UB2 "10K" WP_RP4 150.216,63.906 r270 top (schematic designator RN14)
RN15_UB1 "10K" WP_RP4 113.411,88.163 r180 top (schematic designator RN15)
RN15_UB2 "10K" WP_RP4 161.798,86.893 r180 top (schematic designator RN15)
RN16_UB1 "10K" WP_RP4 108.864,88.214 r180 top (schematic designator RN16)
RN16_UB2 "10K" WP_RP4 157.291,86.893 r180 top (schematic designator RN16)
RN17_UB1 "10K" WP_RP4 98.831,77.775 r90 top (schematic designator RN17)
RN17_UB2 "10K" WP_RP4 146.242,76.174 r90 top (schematic designator RN17)
RN18_UB1 "10K" WP_RP4 104.318,88.265 r180 top (schematic designator RN18)
RN18_UB2 "10K" WP_RP4 152.883,86.918 r180 top (schematic designator RN18)
RN19_UB1 "10K" WP_RP4 57.887,86.893 r0 bottom (schematic designator RN19)
RN19_UB2 "10K" WP_RP4 212.189,89.052 r0 bottom (schematic designator RN19)
RN20_UB1 "10K" WP_RP4 53.391,86.893 r0 bottom (schematic designator RN20)
RN20_UB2 "10K" WP_RP4 207.62,89.078 r0 bottom (schematic designator RN20)
S1 "SW DIP-2" WP_DIP4 109.804,128.397 r270 top
T2 "ACM7060-102" WP_ACM7060 32.69,21.057 r270 top
T3_UB1 "ACM7060-102" WP_ACM7060 35.839,30.15 r90 top (schematic designator T3)
T3_UB2 "ACM7060-102" WP_ACM7060 221.793,30.124 r90 top (schematic designator T3)
T4_UB1 "ACM7060-102" WP_ACM7060 23.47,80.631 r270 top (schematic designator T4)
T4_UB2 "ACM7060-102" WP_ACM7060 241.001,82.626 r270 top (schematic designator T4)
T5 "ACM7060-102" WP_ACM7060 231.267,21.184 r270 top
U1 "HCPL0661" WP_SOIC8 142.9,29.489 r270 top
U2 "HCPL0661" WP_SOIC8 131.851,26.213 r90 top
U3_UB1 "ACPL-W314" WP_SOIC6L 38.176,105.664 r90 bottom (schematic designator U3)
U3_UB2 "ACPL-W314" WP_SOIC6L 225.654,106.045 r90 bottom (schematic designator U3)
U4_UB1 "SN74LVC16245DGGR" WP_TSSOP48 89.205,81.382 r180 top (schematic designator U4)
U4_UB2 "SN74LVC16245DGGR" WP_TSSOP48 172.009,99.974 r0 top (schematic designator U4)
U5 "LRM5-A60H12RB-T2" WP_LRM5-A60H12RB-T2 101,-2.997 r0 top locked
U32_UB1 "AD8397ARZ" WP_SOIC8 103.647,37.897 r180 top (schematic designator U32)
U32_UB2 "AD8397ARZ" WP_SOIC8 153.162,36.297 r90 top (schematic designator U32)
U34_UB1 "SN74LVC16245DGGR" WP_TSSOP48 85.674,49.301 r180 top (schematic designator U34)
U34_UB2 "SN74LVC16245DGGR" WP_TSSOP48 181.178,61.036 r0 top (schematic designator U34)
U35_UB1 "HCPL0661" WP_SOIC8 44.709,113.309 r270 bottom (schematic designator U35)
U35_UB2 "HCPL0661" WP_SOIC8 211.861,113.767 r270 bottom (schematic designator U35)
U37_UB1 "ACPL-W314" WP_SOIC6L 51.44,106.604 r90 top (schematic designator U37)
U37_UB2 "ACPL-W314" WP_SOIC6L 209.6,106.68 r90 bottom (schematic designator U37)
U38_UB1 "ACPL-W314" WP_SOIC6L 65.43,106.451 r90 bottom (schematic designator U38)
U38_UB2 "ACPL-W314" WP_SOIC6L 196.017,106.705 r90 top (schematic designator U38)
U39_UB1 "TPS54531DDAR" WP_SOIC8P 71.069,23.8 r90 top (schematic designator U39)
U39_UB2 "TPS54531DDAR" WP_SOIC8P 187.452,23.368 r90 top (schematic designator U39)
U40_UB1 "ACPL-W314" WP_SOIC6L 57.282,106.604 r90 top (schematic designator U40)
U40_UB2 "ACPL-W314" WP_SOIC6L 204.069,106.68 r90 bottom (schematic designator U40)
U41_UB1 "ACPL-W314" WP_SOIC6L 53.98,106.604 r90 bottom (schematic designator U41)
U41_UB2 "ACPL-W314" WP_SOIC6L 207.06,106.68 r90 top (schematic designator U41)
U42_UB1 "AD2S1210BSTZ" WP_TQ48 109.362,53.772 r180 top locked (schematic designator U42)
U42_UB2 "AD2S1210BSTZ" WP_TQ48 163.297,52.037 r180 top (schematic designator U42)
U43_UB1 "ACPL-W314" WP_SOIC6L 62.896,106.451 r90 top (schematic designator U43)
U43_UB2 "ACPL-W314" WP_SOIC6L 198.557,106.705 r90 bottom (schematic designator U43)
U44_UB1 "ACPL-W314" WP_SOIC6L 45.904,106.604 r90 top (schematic designator U44)
U44_UB2 "ACPL-W314" WP_SOIC6L 212.527,106.705 r90 top (schematic designator U44)
U45_UB1 "ACPL-W314" WP_SOIC6L 59.822,106.604 r90 bottom (schematic designator U45)
U45_UB2 "ACPL-W314" WP_SOIC6L 201.529,106.68 r90 top (schematic designator U45)
U46_UB1 "TPS54531DDAR" WP_SOIC8P 82.423,23.698 r90 top (schematic designator U46)
U46_UB2 "TPS54531DDAR" WP_SOIC8P 174.549,23.317 r90 top (schematic designator U46)
U47_UB1 "TLP127" WP_SOP4 35.159,103.124 r180 bottom (schematic designator U47)
U47_UB2 "TLP127" WP_SOP4 217.653,99.67 r0 bottom (schematic designator U47)
U48_UB1 "OPA2188AIDR" WP_SOIC8 75.951,107.721 r180 top (schematic designator U48)
U48_UB2 "OPA2188AIDR" WP_SOIC8 187.96,108.057 r180 top (schematic designator U48)
U49_UB1 "OPA2188AIDR" WP_SOIC8 75.989,118.821 r180 top (schematic designator U49)
U49_UB2 "OPA2188AIDR" WP_SOIC8 187.985,118.821 r180 top (schematic designator U49)
U50_UB1 "OPA2188AIDR" WP_SOIC8 75.977,96.622 r180 top (schematic designator U50)
U50_UB2 "OPA2188AIDR" WP_SOIC8 187.985,97.155 r180 top (schematic designator U50)
U51_UB1 "AS1117-1V8" WP_SOT223 63.957,42.113 r180 top (schematic designator U51)
U51_UB2 "AS1117-1V8" WP_SOT223 210.617,41.554 r180 top (schematic designator U51)
U52 "SN74AVC4T245PWR" WP_TSSOP16 139.243,79.087 r270 top
U52_UB1 "SN74AVC4T245PWR" WP_TSSOP16 78.74,67.361 r0 top (schematic designator U52)
U52_UB2 "SN74AVC4T245PWR" WP_TSSOP16 180.848,63.856 r180 top (schematic designator U52)
U53_UB1 "SN74LVC16245DGGR" WP_TSSOP48 77.8,69.113 r180 top (schematic designator U53)
U53_UB2 "SN74LVC16245DGGR" WP_TSSOP48 172.745,82.118 r0 top (schematic designator U53)
U54_UB1 "AD2S1210BSTZ" WP_TQ48 114.376,75.697 r180 top (schematic designator U54)
U54_UB2 "AD2S1210BSTZ" WP_TQ48 162.405,73.71 r180 top (schematic designator U54)
U55_UB1 "AVP32F335QP176S" WP_PQFP176 62.54,80.391 r270 top locked (schematic designator U55)
U55_UB2 "AVP32F335QP176S" WP_PQFP176 219.385,80.696 r270 top locked (schematic designator U55)
U56_UB1 "AS1117-2V5" WP_SOT223 120.568,66.243 r270 top (schematic designator U56)
U56_UB2 "AS1117-2V5" WP_SOT223 140.411,58.064 r90 top (schematic designator U56)
U57_UB1 "MCP604T-I/SL" WP_SOIC14 117.495,47.168 r0 top (schematic designator U57)
U57_UB2 "MCP604T-I/SL" WP_SOIC14 139.776,47.219 r0 top (schematic designator U57)
U58_UB1 "SN74LVC4245APWR" WP_TSSOP24 61.626,93.37 r270 top (schematic designator U58)
U58_UB2 "SN74LVC4245APWR" WP_TSSOP24 215.719,94.64 r270 top (schematic designator U58)
U59_UB1 "SN74LVC2G14DCKR" WP_SOT363 30.41,68.453 r0 top (schematic designator U59)
U59_UB2 "SN74LVC2G14DCKR" WP_SOT363 230.804,71.526 r180 top (schematic designator U59)
U60_UB1 "X25040SI-2.7V" WP_SOIC8 48.235,63.551 r0 bottom (schematic designator U60)
U60_UB2 "X25040SI-2.7V" WP_SOIC8 197.785,51.689 r0 top (schematic designator U60)
U61_UB1 "ADM3053BRWZ" WP_SOIC20L 95.052,18.847 r0 bottom (schematic designator U61)
U61_UB2 "ADM3053BRWZ" WP_SOIC20L 161.558,29.921 r180 bottom (schematic designator U61)
U62_UB1 "ADM2582E" WP_SOIC20L 95.103,30.251 r0 top (schematic designator U62)
U62_UB2 "ADM2582E" WP_SOIC20L 161.564,18.517 r180 top (schematic designator U62)
U63 "74HC4052D" WP_SOIC16 131.42,75.082 r180 top
U64 "MCP604T-I/SL" WP_SOIC14 127.635,98.73 r0 top
U65 "AS1117-2V5" WP_SOT223 121.031,103.302 r180 top
U66 "AS1117-3V3" WP_SOT223 132.283,130.378 r0 top
U67 "AD8397ARZ" WP_SOIC8 131.135,60.071 r180 top
U68 "XC9536-10VQ44I" WP_TQFP44 123.8,120.32 r0 top
U69 "MCP604T-I/SL" WP_SOIC14 131.374,37.96 r180 top
UP1 "WRB0505S-3WR2" WP_WRB_CKS 128.626,31.217 r270 top locked
UP4_UB1 "URB2412YMD-15WR3" WP_YMD 43.287,28.219 r0 top (schematic designator UP4)
UP4_UB2 "URB2412YMD-15WR3" WP_YMD 217.125,22.962 r180 top (schematic designator UP4)
UP6_UB1 "URB2415YMD-15WR3" WP_YMD 28.911,94.717 r90 top locked (schematic designator UP6)
UP6_UB2 "URB2415YMD-15WR3" WP_YMD 227.183,95.301 r90 top locked (schematic designator UP6)
X2_UB1 "30MHz" WP_XTAL 51.156,49.784 r180 top (schematic designator X2)
X2_UB2 "30MHz" WP_XTAL 215.443,49.962 r180 top (schematic designator X2)
Y3_UB1 "8.192MHz" WP_5032 112.471,61.163 r90 top (schematic designator Y3)
Y3_UB2 "8.192MHz" WP_5032 166.573,57.988 r90 top (schematic designator Y3)
Y4_UB1 "8.192MHz" WP_5032 117.196,81.712 r90 top (schematic designator Y4)
Y4_UB2 "8.192MHz" WP_5032 166.156,79.546 r90 top (schematic designator Y4)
